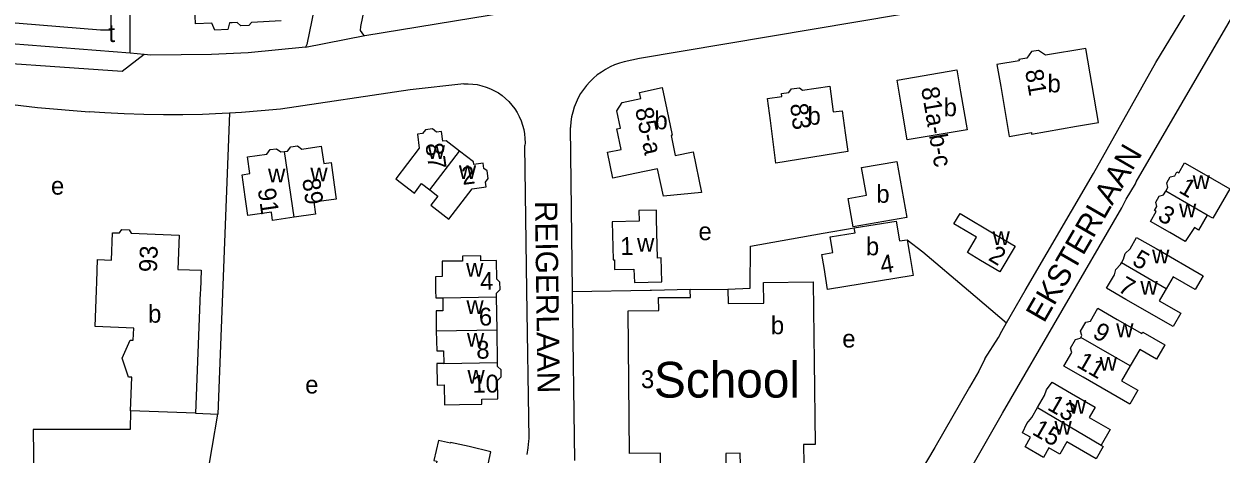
# Model space of a CAD drawing. Extents: x 161775 to 163181, y 382878 to 383925.
# Drawn here: x 162163.3 to 162431.4, y 383537.4 to 383633.7 of the extents above; entities that cross this region are included whole.
import ezdxf

# ---------------------------------------------------------------- set-up
doc = ezdxf.new("R2010")
doc.units = 0
for name, color, linetype in [('BLT_Basislijn', 7, 'Continuous'), ('BLT_Bebouwing', 7, 'Continuous'), ('BLT_Bebouwing_beschrifting', 7, 'Continuous'), ('BLT_Centroide', 7, 'Continuous'), ('BLT_Huisnummer', 7, 'Continuous'), ('BLT_Huisnummer_ tussenligend', 7, 'Continuous'), ('BLT_Huisnummer_reeks', 7, 'Continuous'), ('BLT_Onderverdeling_panden', 7, 'Continuous'), ('BLT_Straatnaam', 7, 'Continuous'), ('BLT_Vlakafsluiter', 7, 'Continuous')]:
    doc.layers.add(name, color=color, linetype=linetype)

msp = doc.modelspace()

# ---------------------------------------------------------------- linework, layer by layer
at = {"layer": 'BLT_Basislijn'}
for p, q in [((162412.37, 383598.34), (162439.64, 383645.18)), ((162190.28, 383626.87), (162187.15, 383627.23)), ((162301.16, 383625.97), (162297.74, 383625.24)), ((162286.19, 383574.02), (162285.69, 383610.53)), ((162275.98, 383574.02), (162275.53, 383606.49)), ((162410.14, 383594.52), (162412.26, 383597.9)), ((162412.26, 383597.9), (162412.37, 383598.34)), ((162382.43, 383546.52), (162409.21, 383592.51)), ((162409.21, 383592.51), (162410.14, 383594.52)), ((162276.45, 383540.83), (162275.98, 383574.02)), ((162286.2, 383573.71), (162286.19, 383574.02)), ((162286.71, 383535.93), (162286.2, 383573.71)), ((162382.34, 383564.94), (162383.35, 383566.81)), ((162201.79, 383546.52), (162206.79, 383546.32)), ((162371.87, 383527.99), (162382.43, 383546.52)), ((162203.76, 383528.62), (162206.79, 383546.32)), ((162367.27, 383538.86), (162363.82, 383532.92))]:
    msp.add_line(p, q, dxfattribs=at)
for points in [[(162270.68, 383789.66), (162255.88, 383716.38), (162238.73, 383633.15), (162238.63, 383632.29), (162239.4, 383631.2), (162239.65, 383631.12)], [(162253.37, 383787.08), (162255.28, 383786.89), (162256.55, 383786.29), (162257.73, 383784.92), (162257.93, 383784.25), (162258.12, 383781.4), (162255, 383766.97), (162226.71, 383629.13), (162226.42, 383628.54)], [(162168.35, 383672.76), (162173.38, 383669.31), (162180.96, 383669.11), (162183.12, 383666.7), (162182.8, 383632.96), (162182.64, 383632.33), (162180.48, 383632.31), (162130.35, 383636.45), (162102.58, 383636.62)], [(162187.15, 383627.23), (162187.11, 383671.22)], [(162387.56, 383574.02), (162402.84, 383600.21), (162416.77, 383625.13), (162425.12, 383638.81), (162425.36, 383639.49), (162425.53, 383641.92), (162425.33, 383642.77), (162424.55, 383644.17), (162424.07, 383644.64), (162422.07, 383645.44), (162419.46, 383645.44), (162408.25, 383644.07), (162301.16, 383625.97)], [(162239.65, 383631.12), (162307.7, 383642.34), (162308.59, 383642.58)], [(162187.15, 383627.23), (162156.61, 383629.61), (162102.16, 383632.48)], [(162190.28, 383626.87), (162185.31, 383623.07), (162144.41, 383625.95), (162097.66, 383627.58), (162097.66, 383627.74), (162096.06, 383627.77), (162065.35, 383627.38), (161992.75, 383624.13)], [(162226.42, 383628.54), (162213.52, 383627.3), (162205.31, 383626.9), (162191.78, 383626.74), (162190.28, 383626.87)], [(162297.74, 383625.24), (162296.66, 383624.94), (162295.6, 383624.55), (162294.57, 383624.1), (162293.58, 383623.57), (162292.63, 383622.97), (162291.72, 383622.31), (162290.86, 383621.58), (162290.05, 383620.8), (162289.31, 383619.96), (162288.62, 383619.07), (162288, 383618.13), (162287.45, 383617.15), (162286.97, 383616.13), (162286.56, 383615.08), (162286.23, 383614.01), (162285.97, 383612.91), (162285.8, 383611.8), (162285.7, 383610.68), (162285.69, 383610.53)], [(162261.82, 383620.33), (162249.8, 383618.95), (162220.8, 383614.66)], [(162261.82, 383620.33), (162262.84, 383620.34), (162263.85, 383620.28), (162264.86, 383620.14), (162265.86, 383619.91), (162266.84, 383619.61), (162267.79, 383619.24), (162268.7, 383618.79), (162269.58, 383618.28), (162270.42, 383617.69), (162271.2, 383617.04), (162271.94, 383616.33), (162272.61, 383615.57), (162273.23, 383614.75), (162273.78, 383613.89), (162274.26, 383612.99), (162274.66, 383612.06), (162275, 383611.09), (162275.25, 383610.11), (162275.43, 383609.1), (162275.53, 383608.09), (162275.55, 383607.07), (162275.53, 383606.49)], [(162156.96, 383616.15), (162166.39, 383615.01), (162177.92, 383614.05)], [(162209.38, 383613.76), (162207.7, 383613.66), (162203.33, 383613.48), (162198.95, 383613.39), (162194.57, 383613.37), (162190.19, 383613.44), (162185.81, 383613.59), (162181.43, 383613.81), (162177.92, 383614.05)], [(162220.8, 383614.66), (162216.44, 383614.25), (162212.08, 383613.91), (162209.38, 383613.76)], [(162320.97, 383574.33), (162325.97, 383574.57), (162326, 383583.98), (162342.28, 383586.83), (162349.28, 383588.04)], [(162361.13, 383585.4), (162364.61, 383582.72), (162374.86, 383574.02)], [(162303.55, 383574.02), (162286.2, 383573.71)], [(162312.55, 383574.25), (162303.83, 383574.03), (162303.55, 383574.02)], [(162374.86, 383574.02), (162383.35, 383566.81)], [(162383.35, 383566.81), (162387.56, 383574.02)], [(162378.51, 383558.7), (162381.57, 383563.51), (162382.34, 383564.94)], [(162378.51, 383558.7), (162377.19, 383555.97), (162375.09, 383552.35)], [(162375.09, 383552.35), (162367.27, 383538.86)], [(162187.22, 383547.07), (162187.13, 383542.85), (162165.4, 383542.85), (162165.64, 383525.92)], [(162275.99, 383537.26), (162276.24, 383538.76), (162276.41, 383540.28), (162276.45, 383540.83)]]:
    msp.add_lwpolyline(points, dxfattribs=at)
at = {"layer": 'BLT_Bebouwing'}
for p, q in [((162209.38, 383613.76), (162206.79, 383546.32)), ((162296.09, 383614.3), (162297.27, 383616.12)), ((162312.55, 383574.25), (162320.97, 383574.33)), ((162312.55, 383574.02), (162312.55, 383574.25)), ((162320.97, 383574.33), (162321, 383571.11)), ((162269.27, 383565.2), (162269.16, 383572.6)), ((162269.39, 383557.88), (162269.27, 383565.2)), ((162201.79, 383546.52), (162187.22, 383547.07))]:
    msp.add_line(p, q, dxfattribs=at)
for points in [[(162209.98, 383634), (162209.35, 383633.96), (162209.03, 383632.52), (162206.05, 383632.35), (162205.41, 383633.92), (162201.79, 383633.78), (162201.6, 383637.34), (162198.46, 383637.17)], [(162220.91, 383634.44), (162214.31, 383634.07), (162213.7, 383633.39), (162211.91, 383633.29), (162211.06, 383634.05), (162209.98, 383634)], [(162399.03, 383610.82), (162403.96, 383611.67), (162401.09, 383628.27), (162392.07, 383626.71), (162390.49, 383627.82), (162388.94, 383627.55), (162387.88, 383626.06), (162386.14, 383625.76), (162386.19, 383625.49), (162381.2, 383624.63), (162382.05, 383619.71), (162383.98, 383608.54), (162388.92, 383609.39), (162388.97, 383609.08), (162399.03, 383610.82)], [(162373.09, 383618.54), (162374.54, 383610.05), (162361.14, 383607.77), (162359.77, 383615.79), (162358.85, 383621.17), (162372.25, 383623.47), (162373.09, 383618.54)], [(162297.27, 383616.12), (162301.47, 383617.01), (162301.18, 383618.41), (162306.26, 383619.49), (162307.3, 383614.6), (162308.52, 383608.83), (162308.23, 383608.77), (162309.18, 383604.27)], [(162347.21, 383609.36), (162347.79, 383605.14), (162331.7, 383602.54), (162330.49, 383612.08), (162329.81, 383617.03), (162333.07, 383617.48), (162332.98, 383618.17), (162334.64, 383618.4), (162335.24, 383619.19), (162336.99, 383619.43), (162337.64, 383618.94), (162343.77, 383619.78), (162344.56, 383614.04), (162346.54, 383614.31), (162347.21, 383609.36)], [(162305.22, 383601.29), (162300.1, 383600.21), (162295.21, 383599.18), (162293.98, 383604.99), (162297.04, 383605.64), (162296.07, 383610.23), (162296.91, 383610.41), (162296.09, 383614.3)], [(162260.89, 383605.26), (162257.87, 383607.58), (162257.13, 383607.48), (162256.84, 383609.66), (162255.74, 383609.52), (162254.83, 383610.22), (162253.24, 383610.01), (162252.62, 383609.21), (162251.46, 383609.06), (162251.87, 383605.88), (162246.61, 383599.04), (162250.76, 383595.84), (162252.39, 383597.96), (162254.2, 383596.57)], [(162223.82, 383590.43), (162219, 383589.74), (162218.74, 383591.56), (162213.5, 383590.81), (162212.9, 383595), (162212.19, 383599.95), (162213.95, 383600.2), (162213.41, 383603.96), (162217.69, 383604.57), (162218.45, 383605.59), (162219.9, 383605.79), (162220.89, 383605.06), (162221.71, 383605.17)], [(162221.71, 383605.17), (162222.35, 383605.27), (162223.08, 383606.24), (162224.59, 383606.46), (162225.59, 383605.71), (162229.9, 383606.33), (162230.46, 383602.44), (162232.1, 383602.68), (162232.81, 383597.73), (162233.27, 383594.5), (162228.26, 383593.78), (162228.64, 383591.12), (162223.82, 383590.43)], [(162254.2, 383596.57), (162256, 383595.18), (162254.45, 383593.16), (162258.5, 383590.03), (162263.72, 383596.82), (162266.81, 383597.22), (162266.67, 383598.29), (162267.28, 383599.08), (162267.05, 383600.83), (162266.35, 383601.36), (162266.2, 383602.55), (162264.05, 383602.27), (162263.97, 383602.88), (162260.89, 383605.26)], [(162309.18, 383604.27), (162313.16, 383605.11), (162315.04, 383595.96), (162306.52, 383595.15), (162305.22, 383601.29)], [(162350.91, 383601.56), (162358.78, 383602.95), (162361.01, 383590.41), (162349, 383588.28), (162347.87, 383594.65), (162351.97, 383595.37), (162350.91, 383601.56)], [(162419.03, 383596.27), (162419.5, 383597.09), (162419.23, 383598.12), (162420.01, 383599.47), (162421.01, 383599.74), (162421.52, 383600.63), (162421.91, 383600.4), (162423.19, 383602.63), (162427.52, 383600.13), (162433.34, 383596.78), (162429.54, 383590.2), (162428.32, 383590.91)], [(162428.32, 383590.91), (162426.38, 383587.55), (162425.43, 383588.1), (162423.39, 383584.99), (162419.93, 383586.99), (162415.6, 383589.49), (162416.9, 383591.73), (162416.52, 383591.95), (162417.03, 383592.83), (162416.76, 383593.82), (162417.53, 383595.16), (162418.54, 383595.43), (162419.03, 383596.27)], [(162306.15, 383576), (162306.02, 383581.32), (162305.22, 383581.3), (162305, 383590.01), (162304.95, 383592.05), (162301.02, 383591.95), (162301.08, 383589.54), (162295.09, 383589.39), (162295.31, 383580.89), (162295.54, 383580.89), (162295.59, 383578.69), (162299.94, 383578.8), (162300.02, 383575.85), (162306.15, 383576)], [(162349.28, 383588.04), (162358.66, 383589.59), (162359.4, 383585.12), (162361.13, 383585.4)], [(162380.97, 383586.52), (162385.26, 383583.95), (162381.83, 383578.21), (162377.54, 383580.78), (162374.59, 383582.54), (162376.64, 383585.97), (162371.58, 383588.99), (162372.96, 383591.31), (162380.97, 383586.52)], [(162179.57, 383574.02), (162179.64, 383575.97), (162179.84, 383580.97), (162182.91, 383580.85), (162183.14, 383586.97), (162184.74, 383586.91), (162185.24, 383587.7), (162186.91, 383587.64), (162187.33, 383586.84), (162198.11, 383586.43), (162197.82, 383578.76), (162203.02, 383578.56), (162202.85, 383574.02)], [(162361.13, 383585.4), (162361.64, 383582.33), (162362.45, 383577.4), (162343.3, 383574.24), (162342.49, 383579.17), (162342, 383582.11), (162344.43, 383582.51), (162343.85, 383586.02), (162349.46, 383586.95), (162349.28, 383588.04)], [(162409.09, 383580.19), (162409.58, 383581.03), (162409.93, 383582.32), (162411.05, 383583.39), (162412.5, 383585.91), (162416.83, 383583.41), (162427.36, 383577.34), (162425.58, 383574.25), (162420.66, 383577.09), (162419.11, 383574.4)], [(162269.75, 383574.02), (162269.95, 383574.23), (162269.93, 383575.92), (162269.24, 383576.59), (162269.17, 383580.75), (162265.62, 383580.69), (162265.61, 383581.79), (162261.51, 383581.73), (162261.53, 383580.63), (162256.96, 383580.56), (162257.02, 383577.14), (162255.47, 383577.11), (162255.52, 383574.02)], [(162406.67, 383574.02), (162405.77, 383574.54), (162407.51, 383577.56), (162407.84, 383578.73), (162408.88, 383579.82), (162409.09, 383580.19)], [(162321, 383571.11), (162328.99, 383571.18), (162328.95, 383575.83), (162340.08, 383575.93), (162340.18, 383563.69), (162340.29, 383558.17), (162340.51, 383539.52), (162337.92, 383539.49), (162337.98, 383535.18), (162323.79, 383535), (162323.75, 383537.58), (162320.5, 383537.54), (162320.54, 383534.87)], [(162187.22, 383547.07), (162187.51, 383554.57), (162186.77, 383554.6), (162185.31, 383558.83), (162187.11, 383562.91), (162187.83, 383562.88), (162187.93, 383565.6), (162179.26, 383565.94), (162179.57, 383574.02)], [(162202.83, 383573.56), (162201.79, 383546.52)], [(162202.85, 383574.02), (162202.83, 383573.56)], [(162255.52, 383574.02), (162255.54, 383572.38), (162257.11, 383572.41)], [(162269.16, 383572.6), (162269.14, 383573.39), (162269.75, 383574.02)], [(162320.54, 383534.87), (162305.88, 383534.75), (162305.85, 383537.56), (162298.94, 383537.5), (162298.66, 383569.5), (162305.48, 383569.56), (162305.45, 383572.43), (162312.57, 383572.49), (162312.55, 383574.02)], [(162418.89, 383574.02), (162417.56, 383571.72), (162422.4, 383568.93), (162420.68, 383565.94), (162410.1, 383572.04), (162406.67, 383574.02)], [(162419.11, 383574.4), (162418.89, 383574.02)], [(162257.11, 383572.41), (162257.16, 383569.49), (162255.62, 383569.47), (162255.68, 383564.98)], [(162399.98, 383563.51), (162400.21, 383563.91), (162399.95, 383564.88), (162401.11, 383566.89), (162402.18, 383567.18), (162403.83, 383570.03), (162408.16, 383567.54), (162413.67, 383564.36), (162413.87, 383564.7), (162418.81, 383561.86), (162416.93, 383558.67), (162413.23, 383560.8), (162411.06, 383557.11)], [(162255.68, 383564.98), (162255.76, 383560.5), (162257.3, 383560.53), (162257.35, 383557.69)], [(162411.06, 383557.11), (162409.14, 383553.79), (162412.79, 383551.68), (162410.98, 383548.55), (162400.52, 383554.58), (162396.19, 383557.08), (162397.95, 383560.13), (162397.7, 383561.07), (162398.83, 383563.04), (162399.87, 383563.32), (162399.98, 383563.51)], [(162257.35, 383557.69), (162255.8, 383557.66), (162255.88, 383552.83), (162257.44, 383552.85), (162257.51, 383548.43), (162260.9, 383548.48), (162265.89, 383548.56), (162265.88, 383549.7), (162269.47, 383549.75), (162269.41, 383553.88), (162270.21, 383554.71), (162270.18, 383556.23), (162269.4, 383556.98), (162269.39, 383557.88)], [(162390.3, 383547.8), (162391.84, 383550.47), (162392.28, 383551.8), (162393.6, 383553.47), (162397.93, 383550.97), (162403.24, 383547.91), (162401.9, 383545.59), (162406.58, 383542.88), (162404.54, 383539.34)], [(162404.54, 383539.34), (162405.01, 383539.07), (162403.43, 383536.32), (162396.89, 383540.09), (162395.3, 383537.34), (162392.84, 383538.76), (162391.62, 383536.64), (162387.5, 383539.01), (162388.73, 383541.13), (162386.93, 383542.16), (162387.87, 383544.22), (162389.01, 383545.56), (162390.3, 383547.8)], [(162263.05, 383539.04), (162258.87, 383540), (162258.83, 383539.83), (162256.15, 383540.45), (162255.1, 383535.91), (162255.79, 383535.75), (162255.02, 383532.41), (162257.36, 383531.87), (162257.19, 383531.16), (162261.32, 383530.21), (162261.18, 383529.61), (162261.72, 383527.86), (162263.36, 383527.11), (162264.59, 383527.48), (162265.73, 383528.19), (162266.08, 383529.72), (162266.81, 383529.55), (162267.81, 383533.86), (162267.03, 383534.04), (162267.92, 383537.91), (162263.05, 383539.04)]]:
    msp.add_lwpolyline(points, dxfattribs=at)
at = {"layer": 'BLT_Onderverdeling_panden'}
for p, q in [((162223.82, 383590.43), (162221.71, 383605.17)), ((162254.2, 383596.57), (162260.89, 383605.26)), ((162428.32, 383590.91), (162419.03, 383596.27)), ((162419.11, 383574.4), (162409.09, 383580.19)), ((162257.11, 383572.41), (162269.16, 383572.6)), ((162255.68, 383564.98), (162269.27, 383565.2)), ((162411.06, 383557.11), (162399.98, 383563.51)), ((162257.35, 383557.69), (162269.39, 383557.88)), ((162390.3, 383547.8), (162404.54, 383539.34))]:
    msp.add_line(p, q, dxfattribs=at)
at = {"layer": 'BLT_Vlakafsluiter'}
msp.add_line((162226.42, 383628.54), (162239.65, 383631.12), dxfattribs=at)

# ---------------------------------------------------------------- texts
at = {"layer": 'BLT_Bebouwing_beschrifting'}
msp.add_text('School', height=8, dxfattribs=at).set_placement((162304.41, 383550.03))
at = {"layer": 'BLT_Centroide'}
for s, p in [('t', (162182.25, 383629.69)), ('b', (162392.54, 383618.41)), ('b', (162369.29, 383613.06)), ('b', (162304.52, 383610.14)), ('b', (162338.79, 383611.16)), ('w', (162253.75, 383603.5)), ('w', (162218, 383598.22)), ('w', (162227.48, 383598.47)), ('w', (162260.73, 383599)), ('e', (162169.39, 383595.5)), ('b', (162354.21, 383593.67)), ('w', (162425.03, 383596.78)), ('w', (162421.99, 383590.44)), ('e', (162314.38, 383585.3)), ('w', (162380.23, 383584.19)), ('w', (162300.62, 383582.7)), ('b', (162351.87, 383581.91)), ('w', (162415.95, 383580.09)), ('w', (162262.35, 383577.09)), ('w', (162413.34, 383573.06)), ('b', (162191.14, 383566.81)), ('w', (162262.42, 383568.78)), ('b', (162330.59, 383564.23)), ('w', (162407.92, 383563.56)), ('w', (162262.53, 383561.44)), ('e', (162346.58, 383561.24)), ('w', (162404.23, 383556.03)), ('w', (162262.65, 383553.16)), ('e', (162226.32, 383550.95)), ('w', (162397.34, 383546.41)), ('w', (162394.1, 383541.69))]:
    msp.add_text(s, height=4, dxfattribs=at).set_placement(p)
at = {"layer": 'BLT_Huisnummer'}
for s, rotation, p in [('81', 279.7913, (162387.5, 383623.26)), ('83', 277.2255, (162334.88, 383615.74)), ('87', 278.1528, (162253.2, 383606.83)), ('2', 7.4306, (162261.59, 383597.66)), ('89', 278.147, (162225.64, 383598.92)), ('1', 330.0206, (162421.71, 383596.11)), ('91', 278.1454, (162215.68, 383596.72)), ('3', 330.0206, (162416.95, 383589.97)), ('1', 1.4392, (162296.9, 383581.94)), ('93', 87.8045, (162193.1, 383578.06)), ('4', 9.3769, (162355.4, 383577.77)), ('2', 329.0952, (162379.07, 383580.96)), ('5', 330.0206, (162411.25, 383579.95)), ('4', 0.9039, (162265.53, 383574.14)), ('7', 330.0206, (162408.06, 383573.96)), ('9', 330.0249, (162402.39, 383563.67)), ('11', 330.0249, (162398.81, 383557.04)), ('10', 0.9054, (162263.77, 383551.09)), ('3', 0.4971, (162301.51, 383552.13)), ('13', 330.0186, (162392.29, 383547.46)), ('15', 330.0306, (162388.88, 383541.92))]:
    msp.add_text(s, height=4, rotation=rotation, dxfattribs=at).set_placement(p)
at = {"layer": 'BLT_Huisnummer_ tussenligend'}
for s, p in [('6', (162265.24, 383566.14)), ('8', (162264.65, 383558.73))]:
    msp.add_text(s, height=4, rotation=0.9039, dxfattribs=at).set_placement(p)
at = {"layer": 'BLT_Huisnummer_reeks'}
for s, rotation, p in [('81a-b-c', 279.6575, (162364.22, 383619.34)), ('85-a', 281.9483, (162300.17, 383614.64))]:
    msp.add_text(s, height=4, rotation=rotation, dxfattribs=at).set_placement(p)
at = {"layer": 'BLT_Straatnaam'}
for s, rotation, p in [('EKSTERLAAN', 59.9092, (162391.75, 383566.56)), ('REIGERLAAN', 270.7988, (162277.76, 383594.06))]:
    msp.add_text(s, height=5, rotation=rotation, dxfattribs=at).set_placement(p)

doc.saveas('drawing.dxf')
